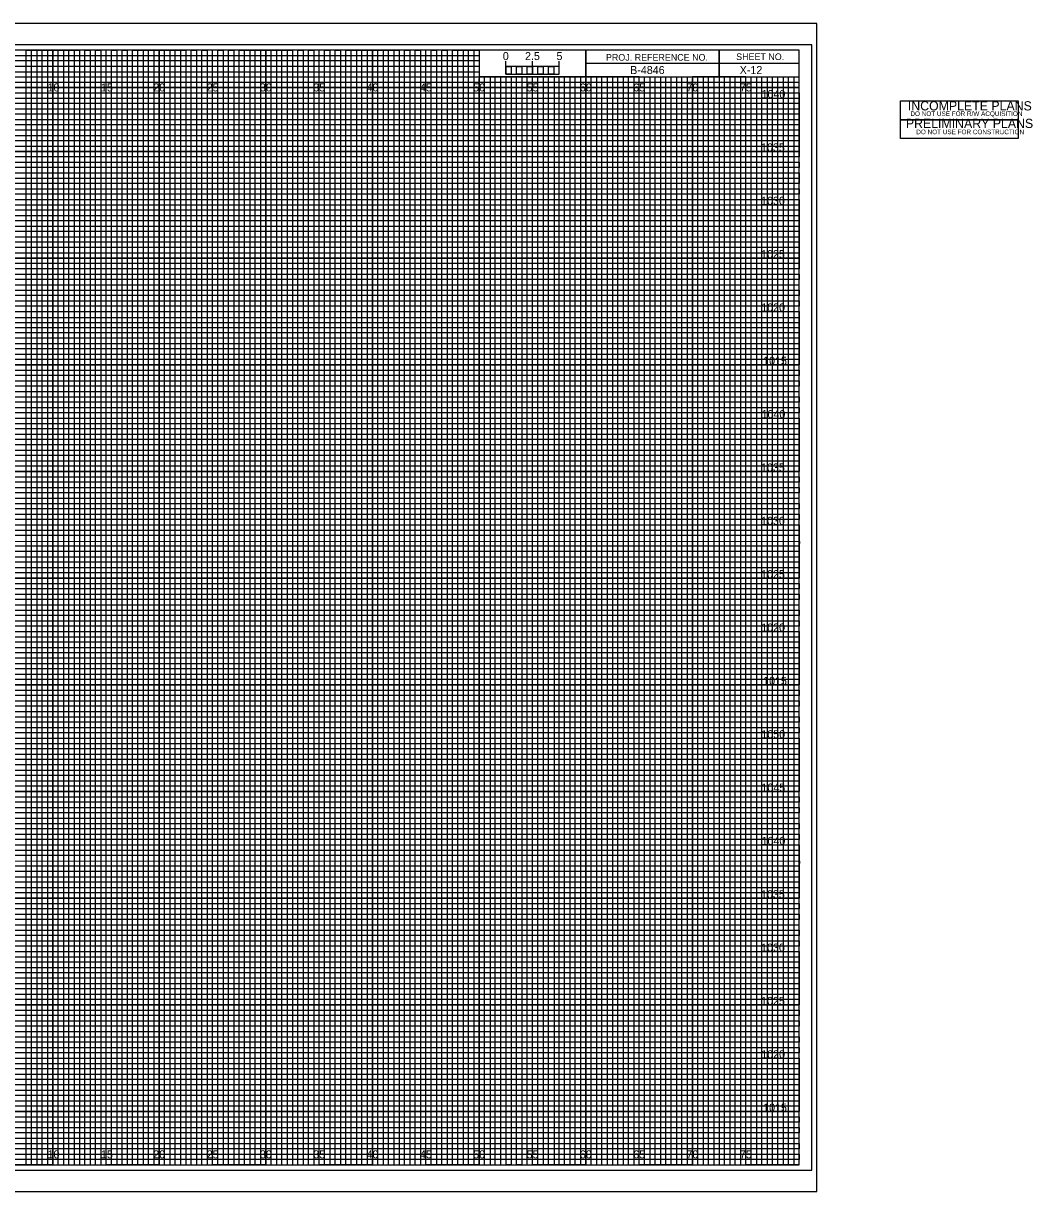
# Model space of a CAD drawing. Extents: x -7 to 182, y 218 to 327.
# Drawn here: x 87.2 to 181.9, y 217.5 to 327 of the extents above; entities that cross this region are included whole.
import ezdxf

# ---------------------------------------------------------------- set-up
doc = ezdxf.new("R2010")
doc.units = 0
for name, color, linetype in [('Default', 7, 'Continuous'), ('Exist Cross Section Cell', 7, 'Continuous'), ('Exist XS Center Line Elevation Label', 7, 'Continuous'), ('Exist XS Ground Line', 7, 'Continuous'), ('Prop CMT Concrete Structures', 7, 'Continuous'), ('Prop CMT Guardrail Graphics', 7, 'Continuous'), ('Prop CMT Guardrail Widen Shoulder', 7, 'Continuous'), ('Prop CMT Pvmt Course 1', 7, 'Continuous'), ('Prop CMT Pvmt Surface', 7, 'Continuous'), ('Prop CMT Pvmt Surface Shoulder', 7, 'Continuous'), ('Prop CMT Shld Paved Course 1', 7, 'Continuous'), ('Prop CMT Shoulder Point', 7, 'Continuous'), ('Prop CMT Slope Grass', 7, 'Continuous'), ('Prop CMT Subgrade Earthwork', 7, 'Continuous'), ('Prop XS SE Text', 7, 'Continuous'), ('Typical Text Label CELL', 7, 'Continuous')]:
    doc.layers.add(name, color=color, linetype=linetype)

msp = doc.modelspace()

# ---------------------------------------------------------------- linework, layer by layer
at = {"layer": 'Default'}
for points in [[(169.51, 317.97), (169.51, 319.73), (180.54, 319.73), (180.54, 317.97)], [(169.51, 316.2), (169.51, 317.97), (180.54, 317.97), (180.54, 316.2)]]:
    msp.add_lwpolyline(points, close=True, dxfattribs=at)
at = {"layer": 'Exist XS Center Line Elevation Label'}
for points in [[(82.5, 220), (87.5, 220), (87.5, 324.5), (92.5, 324.5), (92.5, 220), (97.5, 220), (97.5, 324.5), (102.5, 324.5), (102.5, 220), (107.5, 220), (107.5, 324.5), (112.5, 324.5), (112.5, 220), (117.5, 220), (117.5, 324.5), (122.5, 324.5), (122.5, 220), (127.5, 220), (127.5, 324.5), (129.97, 324.5), (130, 324.5), (130, 322), (132.5, 322), (132.5, 220), (137.5, 220), (137.5, 322), (142.5, 322), (142.5, 220), (147.5, 220), (147.5, 322), (152.5, 322), (152.5, 220), (157.5, 220), (157.5, 322)], [(0, 322), (137.5, 322)], [(0, 312.5), (160, 312.5), (160, 317.5), (0, 317.5)], [(0, 302.5), (160, 302.5), (160, 307.5), (0, 307.5)], [(0, 292.5), (160, 292.5), (160, 297.5), (0, 297.5)], [(0, 282.5), (160, 282.5), (160, 287.5), (0, 287.5)], [(0, 272.5), (160, 272.5), (160, 277.5), (0, 277.5)], [(0, 262.5), (160, 262.5), (160, 267.5), (0, 267.5)], [(0, 252.5), (160, 252.5), (160, 257.5), (0, 257.5)], [(0, 242.5), (160, 242.5), (160, 247.5), (0, 247.5)], [(0, 232.5), (160, 232.5), (160, 237.5), (0, 237.5)], [(0, 222.5), (160, 222.5), (160, 227.5), (0, 227.5)]]:
    msp.add_lwpolyline(points, dxfattribs=at)
at = {"layer": 'Exist XS Ground Line'}
for p, q in [((95, 324.5), (90, 324.5)), ((90, 324.5), (90, 220)), ((95, 220), (95, 324.5)), ((105, 324.5), (100, 324.5)), ((100, 324.5), (100, 220)), ((105, 220), (105, 324.5)), ((115, 324.5), (110, 324.5)), ((110, 324.5), (110, 220)), ((115, 220), (115, 324.5)), ((125, 324.5), (120, 324.5)), ((120, 324.5), (120, 220)), ((125, 220), (125, 324.5)), ((130, 324.5), (130, 220)), ((135, 220), (135, 322)), ((145, 322), (140, 322)), ((140, 322), (140, 220)), ((145, 220), (145, 322)), ((155, 322), (150, 322)), ((150, 322), (150, 220)), ((155, 220), (155, 322)), ((90, 220), (85, 220)), ((100, 220), (95, 220)), ((110, 220), (105, 220)), ((120, 220), (115, 220)), ((130, 220), (125, 220)), ((140, 220), (135, 220)), ((150, 220), (145, 220)), ((160, 220), (155, 220)), ((160, 220), (160, 220))]:
    msp.add_line(p, q, dxfattribs=at)
for points in [[(0, 320), (160, 320), (160, 315), (0, 315)], [(0, 310), (160, 310), (160, 305), (0, 305)], [(0, 300), (160, 300), (160, 295), (0, 295)], [(0, 290), (160, 290), (160, 285), (0, 285)], [(0, 280), (160, 280), (160, 275), (0, 275)], [(0, 270), (160, 270), (160, 265), (0, 265)], [(0, 260), (160, 260), (160, 255), (0, 255)], [(0, 250), (160, 250), (160, 245), (0, 245)], [(0, 240), (160, 240), (160, 235), (0, 235)], [(0, 230), (160, 230), (160, 225), (0, 225)]]:
    msp.add_lwpolyline(points, dxfattribs=at)
at = {"layer": 'Prop CMT Concrete Structures'}
for p, q in [((90, 220), (90, 324.5)), ((95, 220), (95, 324.5)), ((100, 220), (100, 324.5)), ((105, 220), (105, 324.5)), ((110, 220), (110, 324.5)), ((115, 220), (115, 324.5)), ((120, 220), (120, 324.5)), ((125, 220), (125, 324.5)), ((130, 220), (130, 321.84)), ((135, 220), (135, 321.84)), ((140, 220), (140, 321.84)), ((145, 220), (145, 321.84)), ((150, 220), (150, 321.84)), ((155, 220), (155, 321.84)), ((0, 320), (160, 320)), ((0, 315), (160, 315)), ((0, 310), (160, 310)), ((0, 305), (160, 305)), ((0, 300), (160, 300)), ((0, 295), (160, 295)), ((0, 290), (160, 290)), ((0, 285), (160, 285)), ((0, 280), (160, 280)), ((0, 275), (160, 275)), ((0, 270), (160, 270)), ((0, 265), (160, 265)), ((0, 260), (160, 260)), ((0, 255), (160, 255)), ((0, 250), (160, 250)), ((0, 245), (160, 245)), ((0, 240), (160, 240)), ((0, 235), (160, 235)), ((0, 230), (160, 230)), ((0, 225), (160, 225))]:
    msp.add_line(p, q, dxfattribs=at)
at = {"layer": 'Prop CMT Guardrail Widen Shoulder'}
for p, q in [((161.65, 327), (-6.7, 327)), ((-6.7, 217.5), (161.65, 217.5))]:
    msp.add_line(p, q, dxfattribs=at)
at = {"layer": 'Prop CMT Pvmt Course 1'}
msp.add_lwpolyline([(-6.7, 217.5), (161.65, 217.5), (161.65, 327), (-6.7, 327)], close=True, dxfattribs=at)
at = {"layer": 'Prop CMT Pvmt Surface'}
for p, q in [((133.5, 322), (133, 322)), ((133, 322), (133, 220)), ((133.5, 220), (133.5, 322)), ((134.5, 322), (134, 322)), ((134, 322), (134, 220)), ((134.5, 220), (134.5, 322)), ((133, 220), (132.5, 220)), ((134, 220), (133.5, 220))]:
    msp.add_line(p, q, dxfattribs=at)
for points in [[(87.5, 220), (88, 220), (88, 324.5), (88.5, 324.5), (88.5, 220)], [(88.5, 220), (89, 220), (89, 324.5), (89.5, 324.5), (89.5, 220)], [(90, 220), (90.5, 220), (90.5, 324.5), (91, 324.5), (91, 220)], [(91, 220), (91.5, 220), (91.5, 324.5), (92, 324.5), (92, 220)], [(92.5, 220), (93, 220), (93, 324.5), (93.5, 324.5), (93.5, 220)], [(93.5, 220), (94, 220), (94, 324.5), (94.5, 324.5), (94.5, 220)], [(95, 220), (95.5, 220), (95.5, 324.5), (96, 324.5), (96, 220)], [(96, 220), (96.5, 220), (96.5, 324.5), (97, 324.5), (97, 220)], [(97.5, 220), (98, 220), (98, 324.5), (98.5, 324.5), (98.5, 220)], [(98.5, 220), (99, 220), (99, 324.5), (99.5, 324.5), (99.5, 220)], [(100, 220), (100.5, 220), (100.5, 324.5), (101, 324.5), (101, 220)], [(101, 220), (101.5, 220), (101.5, 324.5), (102, 324.5), (102, 220)], [(102.5, 220), (103, 220), (103, 324.5), (103.5, 324.5), (103.5, 220)], [(103.5, 220), (104, 220), (104, 324.5), (104.5, 324.5), (104.5, 220)], [(105, 220), (105.5, 220), (105.5, 324.5), (106, 324.5), (106, 220)], [(106, 220), (106.5, 220), (106.5, 324.5), (107, 324.5), (107, 220)], [(107.5, 220), (108, 220), (108, 324.5), (108.5, 324.5), (108.5, 220)], [(108.5, 220), (109, 220), (109, 324.5), (109.5, 324.5), (109.5, 220)], [(110, 220), (110.5, 220), (110.5, 324.5), (111, 324.5), (111, 220)], [(111, 220), (111.5, 220), (111.5, 324.5), (112, 324.5), (112, 220)], [(112.5, 220), (113, 220), (113, 324.5), (113.5, 324.5), (113.5, 220)], [(113.5, 220), (114, 220), (114, 324.5), (114.5, 324.5), (114.5, 220)], [(115, 220), (115.5, 220), (115.5, 324.5), (116, 324.5), (116, 220)], [(116, 220), (116.5, 220), (116.5, 324.5), (117, 324.5), (117, 220)], [(117.5, 220), (118, 220), (118, 324.5), (118.5, 324.5), (118.5, 220)], [(118.5, 220), (119, 220), (119, 324.5), (119.5, 324.5), (119.5, 220)], [(120, 220), (120.5, 220), (120.5, 324.5), (121, 324.5), (121, 220)], [(121, 220), (121.5, 220), (121.5, 324.5), (122, 324.5), (122, 220)], [(122.5, 220), (123, 220), (123, 324.5), (123.5, 324.5), (123.5, 220)], [(123.5, 220), (124, 220), (124, 324.5), (124.5, 324.5), (124.5, 220)], [(125, 220), (125.5, 220), (125.5, 324.5), (126, 324.5), (126, 220)], [(126, 220), (126.5, 220), (126.5, 324.5), (127, 324.5), (127, 220)], [(127.5, 220), (128, 220), (128, 324.5), (128.5, 324.5), (128.5, 220)], [(128.5, 220), (129, 220), (129, 324.5), (129.5, 324.5), (129.5, 220)], [(130, 220), (130.5, 220), (130.5, 322), (131.01, 322), (131.01, 220)], [(131, 220), (131.5, 220), (131.5, 322), (132, 322), (132, 220)], [(135, 220), (135.49, 220), (135.49, 322), (136, 322), (136, 220)], [(136, 220), (136.5, 220), (136.5, 322), (137.03, 322), (137.03, 220)], [(137.5, 220), (138, 220), (138, 322), (138.5, 322), (138.5, 220)], [(138.5, 220), (139, 220), (139, 322), (139.5, 322), (139.5, 220)], [(140, 220), (140.5, 220), (140.5, 322), (141, 322), (141, 220)], [(141, 220), (141.5, 220), (141.5, 322), (142, 322), (142, 220)], [(142.5, 220), (143, 220), (143, 322), (143.5, 322), (143.5, 220)], [(143.5, 220), (144, 220), (144, 322), (144.5, 322), (144.5, 220)], [(145, 220), (145.5, 220), (145.5, 322), (146, 322), (146, 220)], [(146, 220), (146.5, 220), (146.5, 322), (147, 322), (147, 220)], [(147.5, 220), (148, 220), (148, 322), (148.5, 322), (148.5, 220)], [(148.5, 220), (149, 220), (149, 322), (149.5, 322), (149.5, 220)], [(150, 220), (150.5, 220), (150.5, 322), (151, 322), (151, 220)], [(151, 220), (151.5, 220), (151.5, 322), (152, 322), (152, 220)], [(152.5, 220), (153, 220), (153, 322), (153.5, 322), (153.5, 220)], [(153.5, 220), (154, 220), (154, 322), (154.5, 322), (154.5, 220)], [(155, 220), (155.5, 220), (155.5, 322), (156, 322), (156, 220)], [(156, 220), (156.5, 220), (156.5, 322), (157, 322), (157, 220)], [(157.5, 220), (158, 220), (158, 322), (158.5, 322), (158.5, 220)], [(158.5, 220), (159, 220), (159, 322), (159.5, 322), (159.5, 220)]]:
    msp.add_lwpolyline(points, dxfattribs=at)
at = {"layer": 'Prop CMT Pvmt Surface Shoulder'}
for p, q in [((132.5, 322.25), (132.5, 323.45)), ((132.5, 322.95), (132.5, 323.45)), ((135, 322.25), (135, 323.45)), ((137.5, 322.25), (137.5, 323.45)), ((137.5, 322.95), (137.5, 323.45))]:
    msp.add_line(p, q, dxfattribs=at)
for points in [[(137.5, 322.95), (132.5, 322.95), (132.5, 322.25), (137.5, 322.25)], [(132.5, 322.95), (133, 322.95), (133, 322.25), (132.5, 322.25)], [(133.5, 322.95), (134, 322.95), (134, 322.25), (133.5, 322.25)], [(134.5, 322.95), (135, 322.95), (135, 322.25), (134.5, 322.25)], [(135.5, 322.95), (136, 322.95), (136, 322.25), (135.5, 322.25)], [(136.5, 322.95), (137, 322.95), (137, 322.25), (136.5, 322.25)]]:
    msp.add_lwpolyline(points, close=True, dxfattribs=at)
at = {"layer": 'Prop CMT Shld Paved Course 1'}
for p, q in [((0, 324), (130, 324)), ((130, 323.49), (0, 323.49)), ((130, 324), (130, 323.49)), ((0, 323), (130, 323)), ((130, 322.44), (0, 322.44)), ((130, 323), (130, 322.44)), ((0, 321.5), (160, 321.5))]:
    msp.add_line(p, q, dxfattribs=at)
for points in [[(0, 321), (135, 321), (160, 321), (160, 321), (0, 321)], [(0, 320.5), (160, 320.5), (160, 319.5), (0, 319.5)], [(0, 319), (160, 319), (160, 318.5), (0, 318.49)], [(0, 318), (160, 318), (160, 317), (0, 317)], [(0, 316.5), (160, 316.5), (160, 316), (0, 316)], [(0, 315.5), (160, 315.5), (160, 314.5), (0, 314.5)], [(0, 314), (160, 314), (160, 313.5), (0, 313.5)], [(0, 313), (160, 313), (160, 312), (0, 312)], [(0, 311.5), (160, 311.5), (160, 311), (0, 311)], [(0, 310.5), (160, 310.5), (160, 309.5), (0, 309.5)], [(0, 309), (160, 309), (160, 308.5), (0, 308.5)], [(0, 308), (160, 308), (160, 306.98), (160, 306.5), (160, 306), (0, 306)], [(0, 307), (160, 307), (160, 306.5), (0, 306.5)], [(0, 305.5), (160, 305.5), (160, 304.5), (0, 304.51)], [(0, 304.51), (160, 304.5), (160, 304), (0, 304)], [(0, 303.5), (160, 303.5), (160, 303), (0, 303)], [(0, 302), (160, 302), (160, 301.5), (0, 301.5)], [(0, 301), (160, 301), (160, 300.5), (0, 300.5)], [(-0.04, 299.44), (160, 299.44), (160, 298.94), (-0.04, 298.94)], [(0, 298.5), (160, 298.5), (160, 298), (0, 298)], [(0, 297), (160, 297), (160, 296.5), (0, 296.5)], [(0, 296), (160, 296), (160, 295.5), (0, 295.5)], [(0, 294.5), (160, 294.5), (160, 294), (0, 294)], [(0, 293.5), (160, 293.5), (160, 293), (0, 293)], [(0, 292), (160, 292), (160, 291.5), (0, 291.5)], [(0, 291), (160, 291), (160, 290.5), (0, 290.5)], [(0, 289.5), (160, 289.5), (160, 288.99), (0, 289)], [(0, 288.5), (160, 288.5), (160, 288), (0, 288)], [(0, 287), (160, 287), (160, 286.5), (0, 286.5)], [(0, 286), (160, 286), (160, 285.5), (0, 285.5)], [(0, 284.5), (160, 284.5), (160, 284), (0, 284)], [(0, 283.5), (160, 283.5), (160, 283), (0, 283)], [(0, 282), (160, 282), (160, 281.5), (0, 281.5)], [(0, 281), (160, 281), (160, 280.5), (0, 280.5)], [(0, 279.5), (160, 279.5), (160, 279), (0, 279)], [(0, 278.5), (160.03, 278.45), (160, 278), (0, 278)], [(0, 277), (160, 277), (160, 276.5), (0, 276.5)], [(0, 276), (160, 276), (160, 275.5), (0, 275.5)], [(0, 274.5), (160, 274.5), (160, 274), (0, 274)], [(0, 273.5), (160, 273.5), (160, 273), (0, 273)], [(0, 272), (160, 272), (160, 271.5), (0, 271.5)], [(0, 271), (160, 271), (160, 270.5), (0, 270.5)], [(0, 269.5), (160, 269.5), (160, 269), (0, 269)], [(0, 268.5), (160, 268.5), (160, 268), (0, 268)], [(0, 267), (160, 267), (160, 266.5), (0, 266.5)], [(0, 266), (160, 266), (160, 265.5), (0, 265.5)], [(0, 264.5), (160, 264.5), (160, 264), (0, 264)], [(0, 263.5), (160, 263.5), (160, 263), (0, 263)], [(0, 262), (160, 262), (160, 261.5), (0, 261.5)], [(0, 261), (160, 261), (160, 260.5), (0, 260.5)], [(0, 259.5), (160, 259.5), (160, 258.99), (0, 259)], [(0, 258.5), (160, 258.5), (160, 258), (0, 258)], [(0, 257), (160, 257), (160, 256.5), (0, 256.5)], [(0, 256), (160, 256), (160, 255.5), (0, 255.5)], [(0, 254.5), (160, 254.5), (160, 254), (0, 254)], [(0, 253.5), (160, 253.5), (160, 253), (0, 253)], [(0, 252), (160, 252), (160, 251.5), (0, 251.5)], [(0, 251), (160, 251), (160, 250.5), (0, 250.5)], [(0, 249.5), (160, 249.5), (160, 249), (0, 249)], [(0, 248.5), (160.03, 248.46), (160, 248), (0, 248)], [(0, 247), (160, 247), (160, 246.5), (0, 246.5)], [(0, 246), (160, 246), (160, 245.5), (0, 245.5)], [(0, 244.5), (160, 244.5), (160, 244), (0, 244)], [(0, 243.5), (160, 243.5), (160, 243), (0, 243)], [(0, 242), (160, 242), (160, 241.5), (0, 241.5)], [(0, 241), (160, 241), (160, 240.5), (0, 240.5)], [(0, 239.5), (160, 239.5), (160, 239), (0, 239)], [(0, 238.5), (160, 238.5), (160, 238), (0, 238)], [(0, 237), (160, 237), (160, 236.5), (0, 236.5)], [(0, 236), (160, 236), (160, 235.5), (0, 235.5)], [(0, 234.5), (160, 234.5), (160, 234), (0, 234)], [(0, 233.5), (160, 233.5), (160, 233), (0, 233)], [(0, 232), (160, 232), (160, 231.5), (0, 231.5)], [(0, 231), (160, 231), (160, 230.5), (0, 230.5)], [(0, 229.5), (160, 229.5), (160, 229), (0, 229)], [(0, 228.5), (160, 228.5), (160, 228), (0, 228)], [(0, 227), (160, 227), (160, 226.5), (0, 226.5)], [(0, 226), (160, 226), (160, 225.5), (0, 225.5)], [(0, 224.5), (160, 224.5), (160, 224), (0, 224)], [(0, 223.5), (160, 223.5), (160, 223), (0, 223)], [(0, 222), (160, 222), (160, 221.5), (0, 221.5)], [(0, 221), (160, 221), (160, 220.5), (0, 220.5)]]:
    msp.add_lwpolyline(points, dxfattribs=at)
at = {"layer": 'Prop CMT Slope Grass'}
msp.add_lwpolyline([(-5.4, 219.5), (161.2, 219.5), (161.2, 325), (-5.4, 325)], close=True, dxfattribs=at)
at = {"layer": 'Prop CMT Subgrade Earthwork'}
for p, q in [((152.5, 324.5), (152.5, 322)), ((152.5, 322), (152.5, 324.5)), ((160, 323.25), (140, 323.25)), ((140, 323.25), (140, 322)), ((140, 322), (160, 322))]:
    msp.add_line(p, q, dxfattribs=at)
for points in [[(160, 324.5), (0, 324.5), (0, 220), (160, 220)], [(140, 324.5), (130, 324.5), (130, 322.01), (140, 322.01)], [(160, 324.5), (140, 324.5), (140, 322), (160, 322)]]:
    msp.add_lwpolyline(points, close=True, dxfattribs=at)

# ---------------------------------------------------------------- texts
at = {"layer": 'Default'}
for s, height, p in [('INCOMPLETE PLANS', 0.864, (170.19, 318.84)), ('DO NOT USE FOR R/W ACQUISITION', 0.432, (170.43, 318.32)), ('PRELIMINARY PLANS', 0.864, (170, 317.19)), ('DO NOT USE FOR CONSTRUCTION', 0.432, (170.98, 316.61))]:
    msp.add_text(s, height=height, dxfattribs=at).set_placement(p)
at = {"layer": 'Exist Cross Section Cell'}
for s, p in [('10', (89.52, 320.62)), ('15', (94.53, 320.62)), ('20', (99.43, 320.62)), ('25', (104.44, 320.62)), ('30', (109.43, 320.62)), ('35', (114.44, 320.62)), ('40', (119.43, 320.62)), ('45', (124.44, 320.62)), ('50', (129.43, 320.62)), ('55', (134.44, 320.62)), ('60', (139.43, 320.62)), ('65', (144.44, 320.62)), ('70', (149.43, 320.62)), ('75', (154.44, 320.62)), ('10', (89.52, 220.62)), ('15', (94.53, 220.62)), ('20', (99.43, 220.62)), ('25', (104.44, 220.62)), ('30', (109.43, 220.62)), ('35', (114.44, 220.62)), ('40', (119.43, 220.62)), ('45', (124.44, 220.62)), ('50', (129.43, 220.62)), ('55', (134.44, 220.62)), ('60', (139.43, 220.62)), ('65', (144.44, 220.62)), ('70', (149.43, 220.62)), ('75', (154.44, 220.62))]:
    msp.add_text(s, height=0.75, dxfattribs=at).set_placement(p)
at = {"layer": 'Prop CMT Guardrail Graphics'}
msp.add_text('B-4846', height=0.75, dxfattribs=at).set_placement((144.15, 322.25))
at = {"layer": 'Prop CMT Pvmt Surface Shoulder'}
msp.add_text('0', height=0.75, dxfattribs=at).set_placement((132.21, 323.56))
at = {"layer": 'Prop CMT Shoulder Point'}
for s, p in [('2.5', (134.29, 323.56)), ('5', (137.24, 323.56))]:
    msp.add_text(s, height=0.75, dxfattribs=at).set_placement(p)
at = {"layer": 'Prop CMT Subgrade Earthwork'}
for s, p in [('PROJ. REFERENCE NO.', (141.88, 323.5)), ('SHEET NO.', (154.09, 323.56))]:
    msp.add_text(s, height=0.625, dxfattribs=at).set_placement(p)
at = {"layer": 'Prop XS SE Text'}
msp.add_text('X-12', height=0.75, dxfattribs=at).set_placement((154.42, 322.25))
at = {"layer": 'Typical Text Label CELL'}
for s, p in [('1040', (156.47, 320)), ('1035', (156.42, 315)), ('1030', (156.43, 310)), ('1025', (156.43, 305)), ('1020', (156.44, 300)), ('1015', (156.62, 295)), ('1040', (156.47, 290)), ('1035', (156.42, 285)), ('1030', (156.43, 280)), ('1025', (156.43, 275)), ('1020', (156.44, 270)), ('1015', (156.62, 265)), ('1050', (156.45, 260)), ('1045', (156.46, 255)), ('1040', (156.47, 250)), ('1035', (156.42, 245)), ('1030', (156.43, 240)), ('1025', (156.43, 235)), ('1020', (156.44, 230)), ('1015', (156.62, 225))]:
    msp.add_text(s, height=0.75, dxfattribs=at).set_placement(p)

doc.saveas('drawing.dxf')
